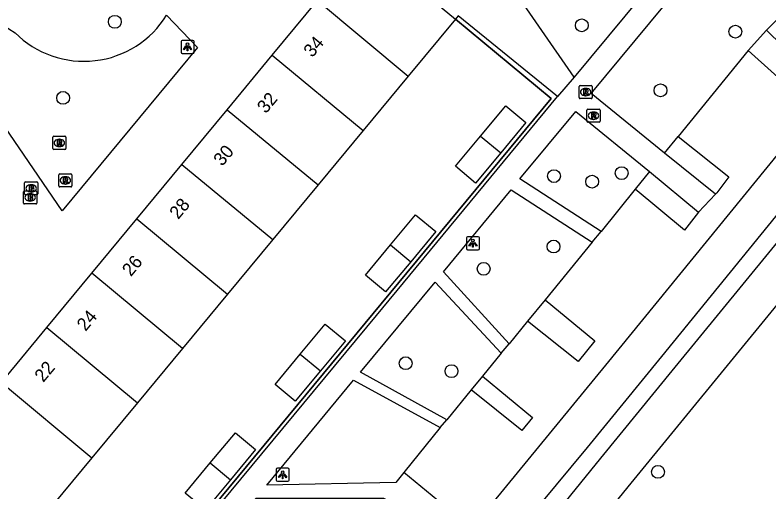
# Model space of a CAD drawing. Extents: x 155275 to 156263, y 382654 to 383635.
# Drawn here: x 155562.9 to 155620.5, y 382845.6 to 382882.1 of the extents above; entities that cross this region are included whole.
import ezdxf

# ---------------------------------------------------------------- set-up
doc = ezdxf.new("R2010")
doc.units = 0
for name, color, linetype in [('IMGEO_Boom', 7, 'Continuous'), ('IMGEO_Brandkraan', 7, 'Continuous'), ('IMGEO_Groenvoorziening', 7, 'Continuous'), ('IMGEO_Hek', 7, 'Continuous'), ('IMGEO_Lichtpunt', 7, 'Continuous'), ('IMGEO_Loofbos', 7, 'Continuous'), ('IMGEO_Pand', 7, 'Continuous'), ('IMGEO_Pand_nummerreeks', 7, 'Continuous'), ('IMGEO_Parkeervlak_halfverhard', 7, 'Continuous'), ('IMGEO_Rijbaan_lokaal_halfverhard', 7, 'Continuous'), ('IMGEO_Rijbaan_lokaal_open', 7, 'Continuous'), ('IMGEO_Rioolput', 7, 'Continuous'), ('IMGEO_Voetpad_open', 7, 'Continuous')]:
    doc.layers.add(name, color=color, linetype=linetype)

msp = doc.modelspace()

# ---------------------------------------------------------------- linework, layer by layer
at = {"layer": 'IMGEO_Boom'}
for centre in [(155570.541, 382881.544), (155606.174, 382881.272), (155617.895, 382880.792), (155612.183, 382876.307), (155566.593, 382875.734), (155609.22, 382869.988), (155604.051, 382869.76), (155606.962, 382869.338), (155604.021, 382864.381), (155598.69, 382862.681), (155592.736, 382855.474), (155596.233, 382854.866), (155611.985, 382847.178)]:
    msp.add_circle(centre, 0.489, dxfattribs=at)
at = {"layer": 'IMGEO_Brandkraan'}
for p, q in [((155563.659, 382868.397), (155563.659, 382869.249)), ((155563.734, 382869.323), (155564.586, 382869.323)), ((155564.66, 382869.249), (155564.66, 382868.397)), ((155564.147, 382869.103), (155564.172, 382869.103)), ((155563.579, 382867.707), (155563.579, 382868.559)), ((155563.654, 382868.633), (155564.506, 382868.633)), ((155564.586, 382868.323), (155563.734, 382868.323)), ((155564.067, 382868.413), (155564.092, 382868.413)), ((155564.17, 382868.543), (155564.145, 382868.543)), ((155564.58, 382868.559), (155564.58, 382867.707)), ((155564.506, 382867.633), (155563.654, 382867.633)), ((155564.09, 382867.853), (155564.065, 382867.853))]:
    msp.add_line(p, q, dxfattribs=at)
for points in [[(155563.659, 382868.397), (155563.659, 382869.249)], [(155563.734, 382869.323), (155564.586, 382869.323)], [(155564.66, 382869.249), (155564.66, 382868.397)], [(155564.007, 382869.023), (155564.007, 382868.623), (155564.22, 382868.623)], [(155564.238, 382869.023), (155564.007, 382869.023)], [(155564.186, 382868.942), (155564.132, 382868.942), (155564.132, 382868.866)], [(155564.132, 382868.866), (155564.185, 382868.866)], [(155564.194, 382868.79), (155564.132, 382868.79), (155564.132, 382868.709)], [(155564.132, 382868.709), (155564.194, 382868.709)], [(155563.579, 382867.707), (155563.579, 382868.559)], [(155563.654, 382868.633), (155564.506, 382868.633)], [(155564.586, 382868.323), (155563.734, 382868.323)], [(155563.927, 382868.333), (155563.927, 382867.933), (155564.14, 382867.933)], [(155564.158, 382868.333), (155563.927, 382868.333)], [(155564.106, 382868.252), (155564.052, 382868.252), (155564.052, 382868.176)], [(155564.052, 382868.176), (155564.105, 382868.176)], [(155564.114, 382868.1), (155564.052, 382868.1), (155564.052, 382868.019)], [(155564.58, 382868.559), (155564.58, 382867.707)], [(155564.506, 382867.633), (155563.654, 382867.633)], [(155564.052, 382868.019), (155564.114, 382868.019)]]:
    msp.add_lwpolyline(points, dxfattribs=at)
for centre, radius, start, end in [((155563.736, 382869.247), 0.0765, 91.55205, 178.44795), ((155563.736, 382869.247), 0.0765, 91.55205, 178.44795), ((155564.584, 382869.247), 0.0765, 1.55205, 88.44795), ((155564.584, 382869.247), 0.0765, 1.55205, 88.44795), ((155564.187, 382868.904), 0.0379, 267.82845, 90.93552), ((155564.195, 382868.749), 0.0404, 269.87594, 90.50774), ((155564.242, 382868.878), 0.145, 59.4692, 91.53667), ((155564.267, 382868.925), 0.0922, 285.51372, 58.15012), ((155564.272, 382868.733), 0.105, 301.31148, 78.98903), ((155563.656, 382868.557), 0.0765, 91.55205, 178.44795), ((155563.656, 382868.557), 0.0765, 91.55205, 178.44795), ((155563.736, 382868.399), 0.0765, 181.55205, 268.44795), ((155563.736, 382868.399), 0.0765, 181.55205, 268.44795), ((155564.107, 382868.214), 0.0379, 267.82845, 90.93552), ((155564.115, 382868.059), 0.0404, 269.87594, 90.50774), ((155564.162, 382868.188), 0.145, 59.4692, 91.53667), ((155564.187, 382868.235), 0.0922, 285.51372, 58.15012), ((155564.192, 382868.043), 0.105, 301.31148, 78.98903), ((155564.226, 382868.874), 0.251, 268.66757, 293.53466), ((155564.504, 382868.557), 0.0765, 1.55205, 88.44795), ((155564.504, 382868.557), 0.0765, 1.55205, 88.44795), ((155564.584, 382868.399), 0.0765, 271.55205, 358.44795), ((155564.584, 382868.399), 0.0765, 271.55205, 358.44795), ((155563.656, 382867.709), 0.0765, 181.55205, 268.44795), ((155563.656, 382867.709), 0.0765, 181.55205, 268.44795), ((155564.146, 382868.184), 0.251, 268.66757, 293.53466), ((155564.504, 382867.709), 0.0765, 271.55205, 358.44795), ((155564.504, 382867.709), 0.0765, 271.55205, 358.44795)]:
    msp.add_arc(centre, radius, start, end, dxfattribs=at)
for centre, major_axis, ratio, start_param, end_param in [((155564.146, 382868.823), (-0.387, 0.002), 0.722429, 4.712389, 7.853982), ((155564.171, 382868.823), (-0.39, 0.002), 0.717154, 1.570796, 4.712389), ((155564.066, 382868.133), (-0.387, 0.002), 0.722429, 4.712389, 7.853982), ((155564.091, 382868.133), (-0.39, 0.002), 0.717154, 1.570796, 4.712389)]:
    msp.add_ellipse(centre, major_axis=major_axis, ratio=ratio, start_param=start_param, end_param=end_param, dxfattribs=at)
at = {"layer": 'IMGEO_Groenvoorziening'}
for points in [[(155596.537, 382881.755), (155603.839, 382875.695), (155573.503, 382838.997), (155565.21, 382841.732), (155564.357, 382842.893)], [(155618.871, 382879.364), (155620.265, 382880.911)], [(155612.485, 382871.506), (155613.537, 382872.79)], [(155611.343, 382870.118), (155610.253, 382868.77)], [(155603.37, 382860.305), (155602.044, 382858.678)], [(155598.6, 382854.487), (155597.738, 382853.431)]]:
    msp.add_lwpolyline(points, dxfattribs=at)
for centre, radius, start, end in [((155574.849, 382899.783), 22.494, 215.00387, 237.99673), ((155568.179, 382885.939), 7.412, 224.88623, 328.43745)]:
    msp.add_arc(centre, radius, start, end, dxfattribs=at)
at = {"layer": 'IMGEO_Hek'}
msp.add_lwpolyline([(155564.357, 382842.893), (155565.21, 382841.732), (155573.503, 382838.997), (155603.839, 382875.695), (155596.537, 382881.755)], dxfattribs=at)
at = {"layer": 'IMGEO_Lichtpunt'}
for p, q in [((155575.592, 382880.034), (155575.592, 382879.227)), ((155575.592, 382880.034), (155575.592, 382879.227)), ((155576.494, 382880.129), (155575.686, 382880.129)), ((155576.494, 382880.129), (155575.686, 382880.129)), ((155576.588, 382879.227), (155576.588, 382880.034)), ((155576.588, 382879.227), (155576.588, 382880.034)), ((155575.686, 382879.133), (155576.494, 382879.133)), ((155575.686, 382879.133), (155576.494, 382879.133)), ((155597.371, 382865.04), (155597.371, 382864.233)), ((155597.371, 382865.04), (155597.371, 382864.233)), ((155598.273, 382865.135), (155597.465, 382865.135)), ((155598.273, 382865.135), (155597.465, 382865.135)), ((155598.367, 382864.233), (155598.367, 382865.04)), ((155598.367, 382864.233), (155598.367, 382865.04)), ((155597.465, 382864.139), (155598.273, 382864.139)), ((155597.465, 382864.139), (155598.273, 382864.139)), ((155583.752, 382847.455), (155582.944, 382847.455)), ((155583.752, 382847.455), (155582.944, 382847.455)), ((155582.85, 382847.36), (155582.85, 382846.553)), ((155582.85, 382847.36), (155582.85, 382846.553)), ((155583.846, 382846.553), (155583.846, 382847.36)), ((155583.846, 382846.553), (155583.846, 382847.36)), ((155582.944, 382846.459), (155583.752, 382846.459)), ((155582.944, 382846.459), (155583.752, 382846.459))]:
    msp.add_line(p, q, dxfattribs=at)
for points in [[(155575.966, 382879.698), (155576.005, 382879.67), (155575.817, 382879.408), (155575.779, 382879.435), (155575.966, 382879.698)], [(155576.068, 382879.65), (155576.115, 382879.65), (155576.115, 382879.328), (155576.068, 382879.328), (155576.068, 382879.65)], [(155576.178, 382879.67), (155576.216, 382879.697), (155576.403, 382879.435), (155576.364, 382879.407), (155576.178, 382879.67)], [(155597.745, 382864.704), (155597.784, 382864.676), (155597.596, 382864.414), (155597.558, 382864.441), (155597.745, 382864.704)], [(155597.847, 382864.656), (155597.894, 382864.656), (155597.894, 382864.334), (155597.847, 382864.334), (155597.847, 382864.656)], [(155597.957, 382864.676), (155597.995, 382864.703), (155598.182, 382864.441), (155598.143, 382864.413), (155597.957, 382864.676)], [(155583.224, 382847.024), (155583.263, 382846.996), (155583.075, 382846.734), (155583.037, 382846.761), (155583.224, 382847.024)], [(155583.326, 382846.976), (155583.373, 382846.976), (155583.373, 382846.654), (155583.326, 382846.654), (155583.326, 382846.976)], [(155583.436, 382846.996), (155583.474, 382847.023), (155583.661, 382846.761), (155583.622, 382846.733), (155583.436, 382846.996)]]:
    msp.add_lwpolyline(points, dxfattribs=at)
for centre in [(155576.091, 382879.832), (155597.87, 382864.838), (155583.349, 382847.158)]:
    msp.add_circle(centre, 0.0994, dxfattribs=at)
for centre, start, end in [((155575.686, 382880.034), 90, 180), ((155575.686, 382880.034), 90, 180), ((155576.494, 382880.034), 0, 90), ((155576.494, 382880.034), 0, 90), ((155575.686, 382879.227), 180, 270), ((155575.686, 382879.227), 180, 270), ((155576.494, 382879.227), 270, 0), ((155576.494, 382879.227), 270, 360), ((155597.465, 382865.04), 90, 180), ((155597.465, 382865.04), 90, 180), ((155598.273, 382865.04), 0, 90), ((155598.273, 382865.04), 0, 90), ((155597.465, 382864.233), 180, 270), ((155597.465, 382864.233), 180, 270), ((155598.273, 382864.233), 270, 0), ((155598.273, 382864.233), 270, 360), ((155582.944, 382847.36), 90, 180), ((155582.944, 382847.36), 90, 180), ((155583.752, 382847.36), 0, 90), ((155583.752, 382847.36), 0, 90), ((155582.944, 382846.553), 180, 270), ((155582.944, 382846.553), 180, 270), ((155583.752, 382846.553), 270, 0), ((155583.752, 382846.553), 270, 360)]:
    msp.add_arc(centre, 0.0946, start, end, dxfattribs=at)
at = {"layer": 'IMGEO_Loofbos'}
msp.add_lwpolyline([(155601.067, 382840.165), (155603.394, 382838.272), (155609.94, 382846.317), (155628.661, 382869.194)], dxfattribs=at)
at = {"layer": 'IMGEO_Pand'}
for points in [[(155586.006, 382883.166), (155589.598, 382887.507), (155596.537, 382881.755)], [(155582.551, 382878.989), (155586.006, 382883.166)], [(155586.006, 382883.166), (155592.934, 382877.404)], [(155596.537, 382881.755), (155592.934, 382877.404)], [(155579.108, 382874.829), (155582.551, 382878.989)], [(155582.551, 382878.989), (155589.489, 382873.244)], [(155592.934, 382877.404), (155589.489, 382873.244)], [(155598.452, 382872.815), (155600.37, 382875.121), (155601.908, 382873.843), (155599.989, 382871.536)], [(155575.659, 382870.66), (155579.108, 382874.829)], [(155579.108, 382874.829), (155586.045, 382869.084)], [(155589.489, 382873.244), (155586.045, 382869.084)], [(155599.989, 382871.536), (155598.07, 382869.229), (155596.533, 382870.508), (155598.452, 382872.815)], [(155598.452, 382872.815), (155599.989, 382871.536)], [(155572.214, 382866.495), (155575.659, 382870.66)], [(155575.659, 382870.66), (155582.594, 382864.917)], [(155586.045, 382869.084), (155582.594, 382864.917)], [(155568.777, 382862.341), (155572.214, 382866.495)], [(155572.214, 382866.495), (155579.144, 382860.75)], [(155591.576, 382864.503), (155593.488, 382866.811), (155595.028, 382865.535), (155593.116, 382863.227)], [(155582.594, 382864.917), (155579.144, 382860.75)], [(155593.116, 382863.227), (155591.204, 382860.918), (155589.664, 382862.194), (155591.576, 382864.503)], [(155591.576, 382864.503), (155593.116, 382863.227)], [(155565.343, 382858.191), (155568.777, 382862.341)], [(155575.708, 382856.601), (155568.777, 382862.341)], [(155579.144, 382860.75), (155575.708, 382856.601)], [(155584.681, 382856.16), (155586.594, 382858.467), (155588.136, 382857.187), (155586.224, 382854.881)], [(155561.883, 382854.009), (155565.343, 382858.191)], [(155565.343, 382858.191), (155572.272, 382852.452)], [(155575.708, 382856.601), (155572.272, 382852.452)], [(155586.224, 382854.881), (155584.31, 382852.573), (155582.768, 382853.852), (155584.681, 382856.16)], [(155584.681, 382856.16), (155586.224, 382854.881)], [(155561.883, 382854.009), (155568.79, 382848.247)], [(155572.272, 382852.452), (155568.79, 382848.247)], [(155577.822, 382847.857), (155579.737, 382850.169), (155581.278, 382848.893), (155579.363, 382846.58)], [(155568.79, 382848.247), (155564.357, 382842.893)], [(155579.363, 382846.58), (155577.448, 382844.268), (155575.907, 382845.544), (155577.822, 382847.857)], [(155577.822, 382847.857), (155579.363, 382846.58)]]:
    msp.add_lwpolyline(points, dxfattribs=at)
at = {"layer": 'IMGEO_Parkeervlak_halfverhard'}
for points in [[(155620.265, 382880.911), (155623.934, 382877.305), (155622.637, 382875.961), (155618.871, 382879.364)], [(155618.871, 382879.364), (155613.537, 382872.79)], [(155613.537, 382872.79), (155617.398, 382869.697), (155616.482, 382868.495), (155616.366, 382868.395)], [(155610.253, 382868.77), (155607.641, 382865.539)], [(155615.071, 382867.009), (155614.004, 382865.641), (155610.253, 382868.77)], [(155606.964, 382864.714), (155603.37, 382860.305)], [(155603.37, 382860.305), (155607.179, 382857.177), (155605.901, 382855.615), (155602.044, 382858.678)], [(155602.044, 382858.678), (155600.643, 382856.959)], [(155600.022, 382856.231), (155598.6, 382854.487)], [(155598.6, 382854.487), (155602.425, 382851.337), (155601.589, 382850.339), (155597.738, 382853.431)], [(155597.738, 382853.431), (155595.872, 382851.144)], [(155595.375, 382850.575), (155592.589, 382847.132)]]:
    msp.add_lwpolyline(points, dxfattribs=at)
msp.add_arc((155637.872, 382863.668), 24.644, 118.2888, 135.59931, dxfattribs=at)
at = {"layer": 'IMGEO_Rijbaan_lokaal_halfverhard'}
msp.add_lwpolyline([(155626.128, 382870.802), (155623.888, 382868.119), (155613.274, 382855.167), (155607.613, 382848.21), (155601.067, 382840.165)], dxfattribs=at)
at = {"layer": 'IMGEO_Rijbaan_lokaal_open'}
for points in [[(155647.708, 382880.7), (155646.999, 382880.578), (155640.779, 382879.513), (155635.384, 382878.472), (155633.955, 382878.163), (155632.562, 382877.717), (155631.218, 382877.14), (155629.98, 382876.463), (155628.811, 382875.675), (155627.72, 382874.781), (155626.716, 382873.79), (155625.809, 382872.71), (155625.006, 382871.55), (155622.738, 382868.856), (155612.247, 382855.989), (155606.592, 382849.042), (155602.968, 382844.675), (155599.969, 382841.061)], [(155597.791, 382842.857), (155608.021, 382855.324), (155621.331, 382871.659)]]:
    msp.add_lwpolyline(points, dxfattribs=at)
at = {"layer": 'IMGEO_Rioolput'}
for p, q in [((155605.973, 382875.752), (155605.973, 382876.604)), ((155606.048, 382876.678), (155606.9, 382876.678)), ((155606.461, 382876.458), (155606.486, 382876.458)), ((155606.974, 382876.604), (155606.974, 382875.752)), ((155606.9, 382875.678), (155606.048, 382875.678)), ((155606.484, 382875.898), (155606.459, 382875.898)), ((155606.568, 382873.949), (155606.568, 382874.801)), ((155606.643, 382874.875), (155607.495, 382874.875)), ((155607.056, 382874.655), (155607.081, 382874.655)), ((155607.569, 382874.801), (155607.569, 382873.949)), ((155607.495, 382873.875), (155606.643, 382873.875)), ((155607.079, 382874.095), (155607.054, 382874.095)), ((155565.81, 382871.873), (155565.81, 382872.725)), ((155565.885, 382872.799), (155566.737, 382872.799)), ((155566.811, 382872.725), (155566.811, 382871.873)), ((155566.298, 382872.579), (155566.323, 382872.579)), ((155566.737, 382871.799), (155565.885, 382871.799)), ((155566.321, 382872.019), (155566.296, 382872.019)), ((155566.264, 382869.007), (155566.264, 382869.859)), ((155566.339, 382869.933), (155567.191, 382869.933)), ((155567.265, 382869.859), (155567.265, 382869.007)), ((155566.752, 382869.713), (155566.777, 382869.713)), ((155567.191, 382868.933), (155566.339, 382868.933)), ((155566.775, 382869.153), (155566.75, 382869.153))]:
    msp.add_line(p, q, dxfattribs=at)
for points in [[(155605.973, 382875.752), (155605.973, 382876.604)], [(155606.048, 382876.678), (155606.9, 382876.678)], [(155606.562, 382876.376), (155606.31, 382876.378), (155606.31, 382875.978)], [(155606.31, 382875.978), (155606.434, 382875.978), (155606.434, 382876.14), (155606.445, 382876.14)], [(155606.488, 382876.297), (155606.434, 382876.297), (155606.434, 382876.216)], [(155606.434, 382876.216), (155606.486, 382876.216)], [(155606.974, 382876.604), (155606.974, 382875.752)], [(155606.9, 382875.678), (155606.048, 382875.678)], [(155606.492, 382876.111), (155606.563, 382875.978), (155606.703, 382875.978), (155606.638, 382876.104)], [(155606.568, 382873.949), (155606.568, 382874.801)], [(155606.643, 382874.875), (155607.495, 382874.875)], [(155607.157, 382874.573), (155606.905, 382874.575), (155606.905, 382874.175)], [(155607.083, 382874.494), (155607.029, 382874.494), (155607.029, 382874.413)], [(155607.029, 382874.413), (155607.081, 382874.413)], [(155607.569, 382874.801), (155607.569, 382873.949)], [(155607.495, 382873.875), (155606.643, 382873.875)], [(155606.905, 382874.175), (155607.029, 382874.175), (155607.029, 382874.337), (155607.04, 382874.337)], [(155607.087, 382874.308), (155607.158, 382874.175), (155607.298, 382874.175), (155607.233, 382874.301)], [(155565.81, 382871.873), (155565.81, 382872.725)], [(155565.885, 382872.799), (155566.737, 382872.799)], [(155566.811, 382872.725), (155566.811, 382871.873)], [(155566.399, 382872.497), (155566.147, 382872.499), (155566.147, 382872.099)], [(155566.147, 382872.099), (155566.271, 382872.099), (155566.271, 382872.261), (155566.282, 382872.261)], [(155566.325, 382872.418), (155566.271, 382872.418), (155566.271, 382872.337)], [(155566.271, 382872.337), (155566.323, 382872.337)], [(155566.329, 382872.232), (155566.4, 382872.099), (155566.54, 382872.099), (155566.475, 382872.225)], [(155566.737, 382871.799), (155565.885, 382871.799)], [(155566.264, 382869.007), (155566.264, 382869.859)], [(155566.339, 382869.933), (155567.191, 382869.933)], [(155567.265, 382869.859), (155567.265, 382869.007)], [(155566.853, 382869.631), (155566.601, 382869.633), (155566.601, 382869.233)], [(155566.601, 382869.233), (155566.725, 382869.233), (155566.725, 382869.395), (155566.736, 382869.395)], [(155566.779, 382869.552), (155566.725, 382869.552), (155566.725, 382869.471)], [(155566.725, 382869.471), (155566.777, 382869.471)], [(155566.783, 382869.366), (155566.854, 382869.233), (155566.994, 382869.233), (155566.929, 382869.359)], [(155567.191, 382868.933), (155566.339, 382868.933)]]:
    msp.add_lwpolyline(points, dxfattribs=at)
for centre, radius, start, end in [((155606.05, 382876.602), 0.0765, 91.55205, 178.44795), ((155606.05, 382876.602), 0.0765, 91.55205, 178.44795), ((155606.444, 382876.087), 0.0533, 26.02933, 88.69889), ((155606.47, 382876.405), 0.19, 274.7715, 282.96867), ((155606.494, 382876.201), 0.0964, 77.00612, 93.18647), ((155606.508, 382876.258), 0.0378, 276.66336, 79.67722), ((155606.561, 382876.266), 0.109, 350.36119, 89.41601), ((155606.559, 382876.266), 0.112, 277.58423, 350.98172), ((155606.543, 382876.051), 0.108, 29.51342, 73.79051), ((155606.898, 382876.602), 0.0765, 1.55205, 88.44795), ((155606.898, 382876.602), 0.0765, 1.55205, 88.44795), ((155606.05, 382875.754), 0.0765, 181.55205, 268.44795), ((155606.05, 382875.754), 0.0765, 181.55205, 268.44795), ((155606.898, 382875.754), 0.0765, 271.55205, 358.44795), ((155606.898, 382875.754), 0.0765, 271.55205, 358.44795), ((155606.645, 382874.799), 0.0765, 91.55205, 178.44795), ((155606.645, 382874.799), 0.0765, 91.55205, 178.44795), ((155607.065, 382874.602), 0.19, 274.7715, 282.96867), ((155607.089, 382874.398), 0.0964, 77.00612, 93.18647), ((155607.103, 382874.455), 0.0378, 276.66336, 79.67722), ((155607.156, 382874.463), 0.109, 350.36119, 89.41601), ((155607.154, 382874.463), 0.112, 277.58423, 350.98172), ((155607.493, 382874.799), 0.0765, 1.55205, 88.44795), ((155607.493, 382874.799), 0.0765, 1.55205, 88.44795), ((155606.645, 382873.951), 0.0765, 181.55205, 268.44795), ((155606.645, 382873.951), 0.0765, 181.55205, 268.44795), ((155607.039, 382874.284), 0.0533, 26.02933, 88.69889), ((155607.138, 382874.248), 0.108, 29.51342, 73.79051), ((155607.493, 382873.951), 0.0765, 271.55205, 358.44795), ((155607.493, 382873.951), 0.0765, 271.55205, 358.44795), ((155565.887, 382872.723), 0.0765, 91.55205, 178.44795), ((155565.887, 382872.723), 0.0765, 91.55205, 178.44795), ((155566.735, 382872.723), 0.0765, 1.55205, 88.44795), ((155566.735, 382872.723), 0.0765, 1.55205, 88.44795), ((155566.281, 382872.208), 0.0533, 26.02933, 88.69889), ((155566.307, 382872.526), 0.19, 274.7715, 282.96867), ((155566.331, 382872.322), 0.0964, 77.00612, 93.18647), ((155566.345, 382872.379), 0.0378, 276.66336, 79.67722), ((155566.398, 382872.387), 0.109, 350.36119, 89.41601), ((155566.396, 382872.387), 0.112, 277.58423, 350.98172), ((155566.38, 382872.172), 0.108, 29.51342, 73.79051), ((155565.887, 382871.875), 0.0765, 181.55205, 268.44795), ((155565.887, 382871.875), 0.0765, 181.55205, 268.44795), ((155566.735, 382871.875), 0.0765, 271.55205, 358.44795), ((155566.735, 382871.875), 0.0765, 271.55205, 358.44795), ((155566.341, 382869.857), 0.0765, 91.55205, 178.44795), ((155566.341, 382869.857), 0.0765, 91.55205, 178.44795), ((155567.189, 382869.857), 0.0765, 1.55205, 88.44795), ((155567.189, 382869.857), 0.0765, 1.55205, 88.44795), ((155566.735, 382869.342), 0.0533, 26.02933, 88.69889), ((155566.761, 382869.66), 0.19, 274.7715, 282.96867), ((155566.785, 382869.456), 0.0964, 77.00612, 93.18647), ((155566.799, 382869.513), 0.0378, 276.66336, 79.67722), ((155566.852, 382869.521), 0.109, 350.36119, 89.41601), ((155566.85, 382869.521), 0.112, 277.58423, 350.98172), ((155566.834, 382869.306), 0.108, 29.51342, 73.79051), ((155566.341, 382869.009), 0.0765, 181.55205, 268.44795), ((155566.341, 382869.009), 0.0765, 181.55205, 268.44795), ((155567.189, 382869.009), 0.0765, 271.55205, 358.44795), ((155567.189, 382869.009), 0.0765, 271.55205, 358.44795)]:
    msp.add_arc(centre, radius, start, end, dxfattribs=at)
for centre, major_axis, ratio, start_param, end_param in [((155606.46, 382876.178), (-0.387, 0.002), 0.722429, 4.712389, 7.853982), ((155606.485, 382876.178), (-0.39, 0.002), 0.717154, 1.570796, 4.712389), ((155607.055, 382874.375), (-0.387, 0.002), 0.722429, 4.712389, 7.853982), ((155607.08, 382874.375), (-0.39, 0.002), 0.717154, 1.570796, 4.712389), ((155566.297, 382872.299), (-0.387, 0.002), 0.722429, 4.712389, 7.853982), ((155566.322, 382872.299), (-0.39, 0.002), 0.717154, 1.570796, 4.712389), ((155566.751, 382869.433), (-0.387, 0.002), 0.722429, 4.712389, 7.853982), ((155566.776, 382869.433), (-0.39, 0.002), 0.717154, 1.570796, 4.712389)]:
    msp.add_ellipse(centre, major_axis=major_axis, ratio=ratio, start_param=start_param, end_param=end_param, dxfattribs=at)
at = {"layer": 'IMGEO_Voetpad_open'}
for points in [[(155612.485, 382871.506), (155606.896, 382876.059), (155629.399, 382903.229), (155638.564, 382914.347)], [(155618.439, 382892.81), (155605.583, 382877.325)], [(155574.495, 382882.059), (155576.86, 382879.581), (155566.513, 382867.099), (155554.075, 382885.324), (155556.424, 382886.88)], [(155605.583, 382877.325), (155600.196, 382885.12), (155599.797, 382885.697), (155599.981, 382885.92)], [(155604.331, 382875.831), (155596.729, 382881.999), (155596.537, 382881.755)], [(155605.583, 382877.325), (155604.331, 382875.831)], [(155599.543, 382834.722), (155597.975, 382835.119), (155598.119, 382837.48), (155598.283, 382839.928), (155596.695, 382841.522), (155596.457, 382841.761), (155595.092, 382843.138), (155591.059, 382845.145), (155585.773, 382845.15), (155582.468, 382845.138), (155581.289, 382845.15), (155578.417, 382841.658), (155579.737, 382841.319), (155577.044, 382838.043), (155573.866, 382839.028), (155590.509, 382859.114), (155604.331, 382875.831)], [(155607.641, 382865.539), (155601.447, 382869.544), (155605.73, 382874.69), (155611.343, 382870.118)], [(155616.366, 382868.395), (155612.485, 382871.506)], [(155611.343, 382870.118), (155615.071, 382867.009)], [(155600.643, 382856.959), (155595.617, 382862.458), (155600.794, 382868.709), (155606.964, 382864.714)], [(155615.071, 382867.009), (155616.366, 382868.395)], [(155606.964, 382864.714), (155607.641, 382865.539)], [(155595.872, 382851.144), (155589.292, 382854.802), (155594.997, 382861.659), (155600.022, 382856.231)], [(155600.022, 382856.231), (155600.643, 382856.959)], [(155592.589, 382847.132), (155591.976, 382846.374), (155582.131, 382846.165), (155588.764, 382854.19), (155595.375, 382850.575)], [(155595.375, 382850.575), (155595.872, 382851.144)], [(155597.791, 382842.857), (155592.589, 382847.132)]]:
    msp.add_lwpolyline(points, dxfattribs=at)

# ---------------------------------------------------------------- texts
at = {"layer": 'IMGEO_Pand_nummerreeks'}
for s, p in [('34', (155585.611, 382878.77)), ('32', (155582.067, 382874.487)), ('30', (155578.738, 382870.464)), ('28', (155575.38, 382866.405)), ('26', (155571.767, 382862.037)), ('24', (155568.31, 382857.86)), ('22', (155565.083, 382853.959))]:
    msp.add_text(s, height=1, rotation=50.19683, dxfattribs=at).set_placement(p)

doc.saveas('drawing.dxf')
